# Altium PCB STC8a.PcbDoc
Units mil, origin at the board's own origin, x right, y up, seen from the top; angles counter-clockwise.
Board outline 3926.03 x 2520.03 mil, 2 copper layers (Top Layer, Bottom Layer); 127 components, 97 nets, 398 pads, 107 vias.
Unrouted connection lines stored in the file: 1.
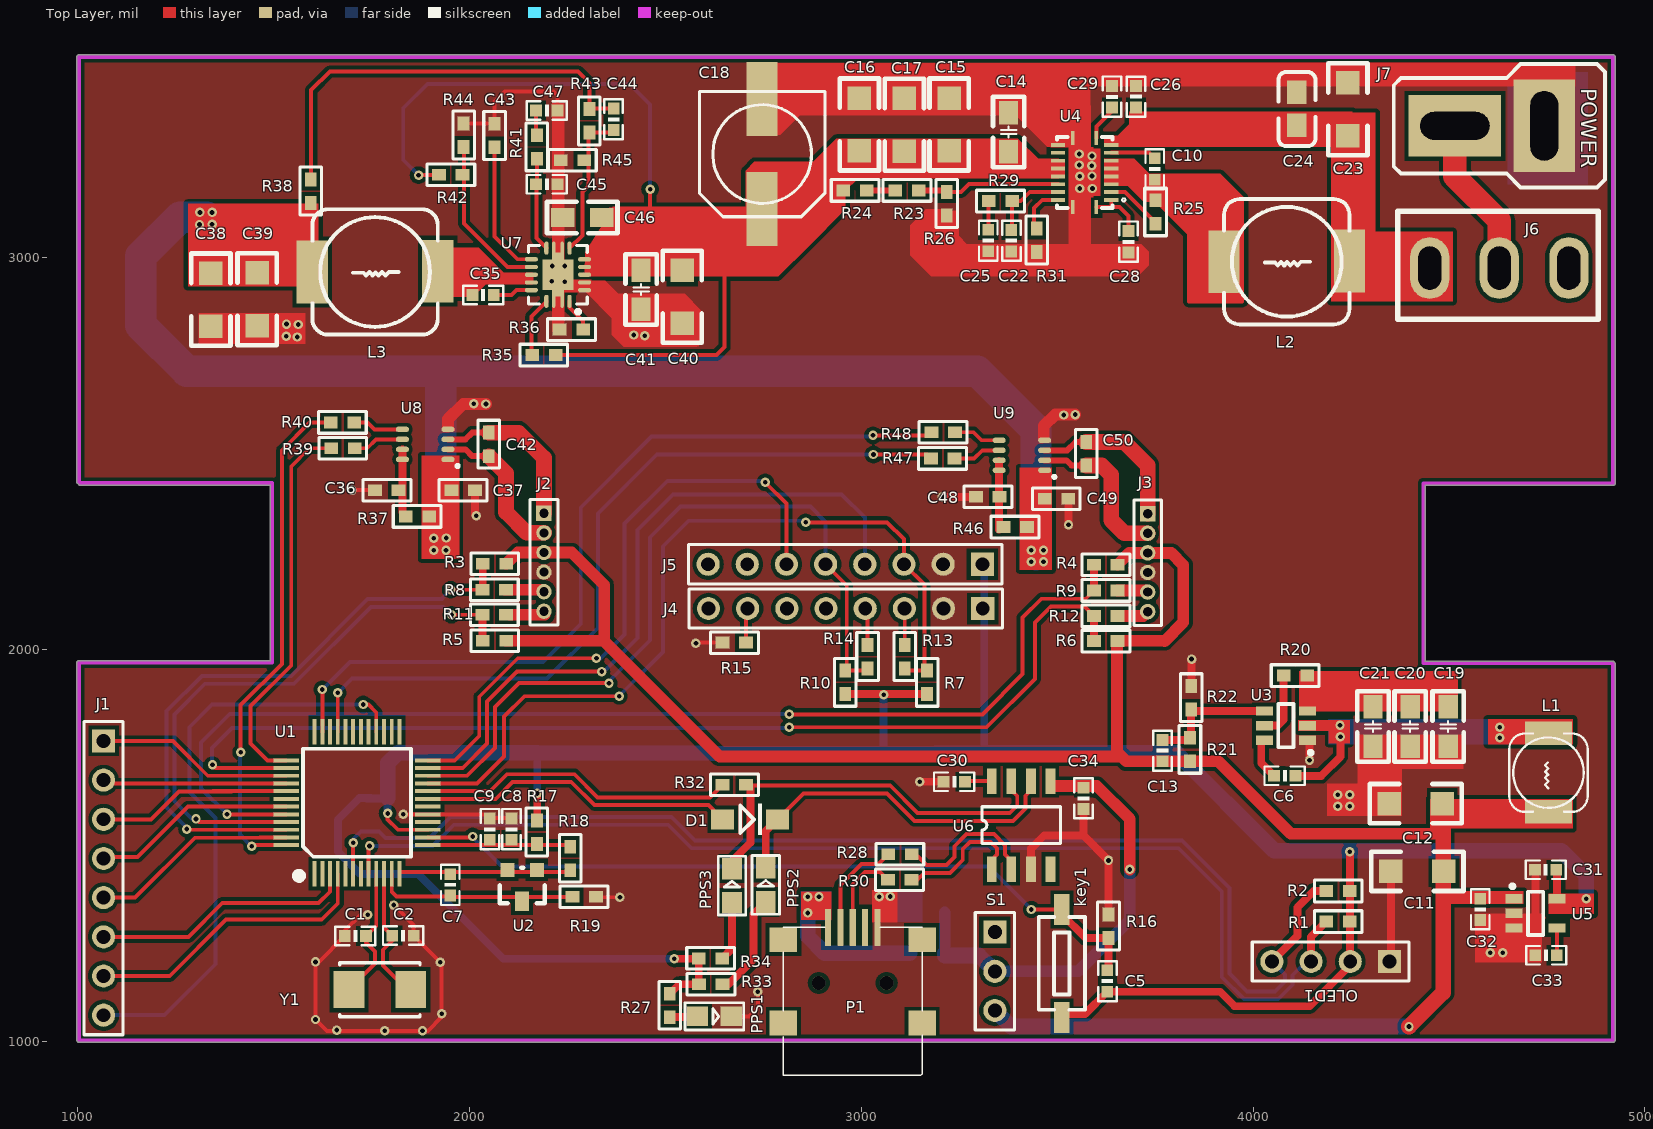
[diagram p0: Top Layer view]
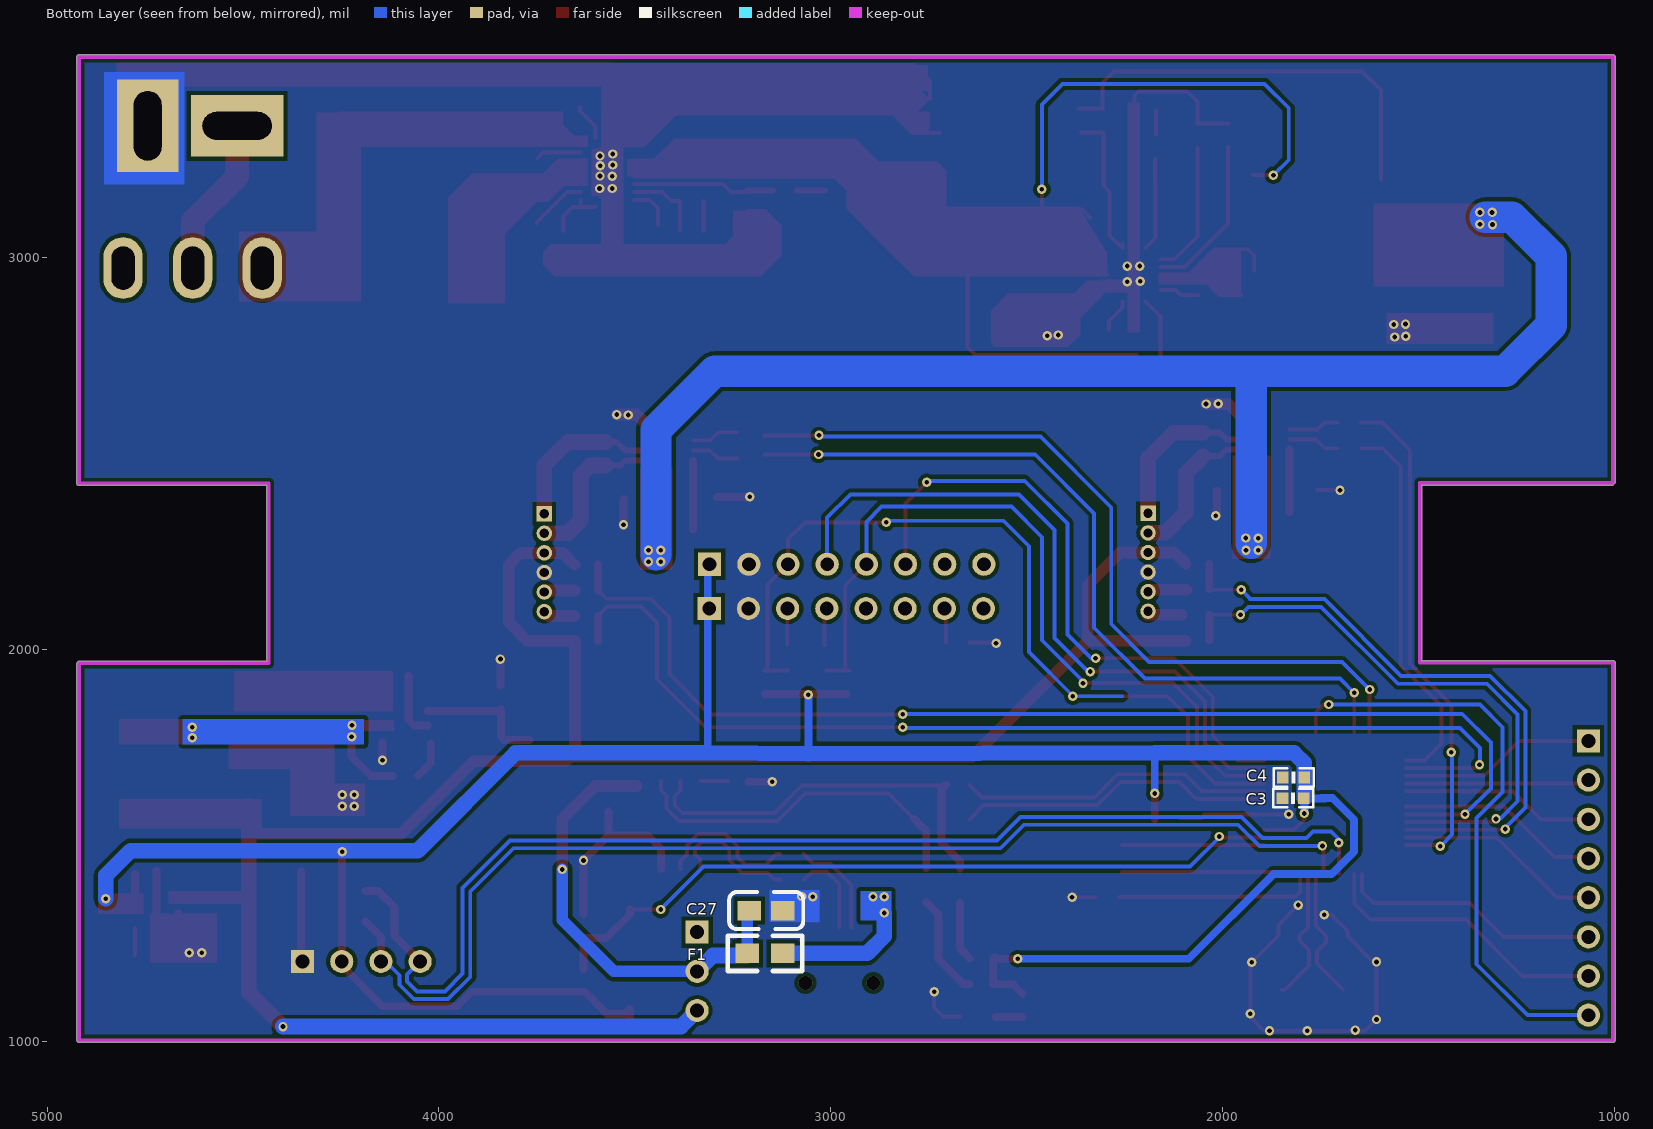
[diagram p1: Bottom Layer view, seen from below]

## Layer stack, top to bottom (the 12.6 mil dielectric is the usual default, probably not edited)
Top Solder: solder mask 0.4, Solder Resist, Dk 3.5
Top Layer: signal copper 1.4
Dielectric 1: dielectric 12.6, FR-4, Dk 4.8
Bottom Layer: signal copper 1.4
Bottom Solder: solder mask 0.4, Solder Resist, Dk 3.5

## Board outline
1003,997.99 cw(c1003,1003) 997.99,1003 997.99,1965 cw(c1003,1965) 998.09,1966 cw(c1003,1967) 1003,1972.02 1490.98,1972.02 1490.98,2419.99 1006,2419.99 cw(c1006,2425) 1002.44,2421.47 1002.45,2421.45 999.45,2424.45 999.47,2424.44 cw(c1003,2428) 997.99,2428 997.99,3513 cw(c1003,3513) 1003,3518.01 4919,3518.01 cw(c4919,3513) 4924.02,3513 4924.02,2424 cw(c4919,2424) 4919,2418.99 4440.02,2418.99 4440.02,1971.02 4917,1971.02 cw(c4917,1966) 4921.4,1968.4 cw(c4919,1964) 4924.02,1964 4924.02,1003 cw(c4919,1003) 4919,997.99

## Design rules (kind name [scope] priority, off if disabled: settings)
Clearance [All] p1: gap=10
PlaneConnect [All] p1: planeconnectstyle=Direct reliefexpansion=20 reliefentries=4 reliefconductorwidth=10 reliefairgap=10
PolygonConnect [All] p1: connectstyle=Direct reliefconductorwidth=10 reliefentries=4 polygonreliefangle="90 Angle" airgapwidth=10
RoutingVias [All] p1: holewidth=28 width=50 viastyle="Through Hole" minholewidth=28 minwidth=50 maxholewidth=28 maxwidth=50
SolderMaskExpansion [All] p1: expansion=4
Width [All] p1: maxlimit=80 minlimit=10 preferedwidth=80 toplayer_maxwidth=60 toplayer_prefwidth=10 minimp=50.000000 maximp=50.000000 favimp=50.000000
29 further rules are at their usual default settings.

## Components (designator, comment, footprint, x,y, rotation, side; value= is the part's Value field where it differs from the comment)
C1 "22PF" 0603-C 1736,1269 r180 top
C2 "22PF" 0603-C 1803,1270 r0 top
C3 "" 0603-C 1847,1621 r180 bottom
C4 "" 0603-C 1846,1674 r180 bottom
C5 "104" 0603-C 3628.06,1181.5 r270 top
C6 "" 0603-c 4108,1678 r180 top
C7 "100nf" 0603-C 1951,1427 r270 top
C8 "10UF" 0603-C 2106.94,1514.5 r90 top
C9 "100NF" 0603-C 2051.94,1514.5 r90 top
C10 "" 0603-c 3749,3254 r270 top
C11 "" 1206 4352,1434 r0 top
C12 "" 1206 4348,1607 r0 top
C13 "" 0603-c 3769.06,1769.5 r270 top
C14 "" 0805C 3376,3371 r270 top
C15 "" 1206 3224,3408 r270 top
C16 "" 1206 2995,3408 r270 top
C17 "" 1206 3110,3407 r270 top
C18 "" CC88 2747,3265 r90 top
C19 "" 0805c 4498,1854 r270 top
C20 "" 0805c 4401,1854 r270 top
C21 "" 0805c 4306,1854 r270 top
C22 "" 0603-C 3383,3071 r270 top
C23 "" 1206 4242,3312 r90 top
C24 "" 0805-c 4112,3423 r270 top
C25 "" 0603-C 3324.06,3071.5 r270 top
C26 "" 0603-c 3701.06,3438.5 r270 top
C27 "10uF" 0805-C 3208,1334 r180 bottom
C28 "" 0603-c 3682,3014 r90 top
C29 "" 0603-C 3640,3384 r90 top
C30 "0.1uf" 0603-C 3264.5,1662.94 r180 top
C31 "" 0603-C 4719.5,1438.06 r0 top
C32 "" 0603-C 4580,1310 r90 top
C33 "" 0603-C 4720.5,1220.06 r0 top
C34 "0.1uf" 0603-C 3567,1593 r90 top
C35 "" 0603-c 2007.5,2905.06 r0 top
C36 "0.1UF" 0603-r 1819,2407 r180 top
C37 "0.1UF" 0603-r 1954,2407 r0 top
C38 "" 1206 1340,2826 r90 top
C39 "" 1206 1458,2827 r90 top
C40 "" 1206 2543,2968 r270 top
C41 "" 0805c 2438,2869 r90 top
C42 "104" 0603-r 2049,2554 r270 top
C43 "" 0603-r 2064,3342 r270 top
C44 "" 0603-c 2367.94,3326.5 r90 top
C45 "" 0603-c 2224.5,3187.94 r180 top
C46 "" 0805r 2238,3103 r0 top
C47 "" 0603-c 2224.5,3375.94 r180 top
C48 "0.1UF" 0603-r 3353,2390 r180 top
C49 "0.1UF" 0603-r 3468,2385 r0 top
C50 "104" 0603-r 3574,2530 r270 top
D1 "二极管" DIODE_SOP 2646,1567 r0 top
F1 "500mA保险丝" "0805 - duplicate" 3123,1224.94 r0 bottom
J1 "CON8" HDR1X8 1066,1767 r270 top
J2 "CON6" MHDR1X6 2190,2348 r270 top
J3 "CON6" MHDR1X6 3731,2347 r270 top
J4 "CON8" HDR1X8 3310,2105 r180 top
J5 "CON8" HDR1X8 3309,2218 r180 top
J6 "主开关" 拨动开关 4626,2979 r90 top
J7 "T插" T型头 4642,3329 r180 top
key1 "KEY" KEY 3512,1199 r0 top
L1 "Inductor" L5*5 4754,1586 r90 top
L2 "PIMB   0630" L8*8 4246,2990 r180 top
L3 "Inductor" L8*8 1919,2964 r180 top
OLED1 "CON4" HDR1X4 4348,1204 r180 top
P1 "USB_Micro" "USB_MINI - duplicate" 2978.16,913.14 r90 top
PPS1 "LED" 0805-LED 2629,1064 r0 top
PPS2 "LED" 0805-LED 2756,1403.63 r90 top
PPS3 "LED" 0805-LED 2670,1401.64 r90 top
R1 "" 0603-R 4247,1306 r180 top
R2 "" 0603-R 4247,1384 r180 top
R3 "10K" 0603-R 2094,2219 r180 top
R4 "10K" 0603-R 3654,2217 r180 top
R5 "10K" 0603-R 2094,2023 r180 top
R6 "10K" 0603-R 3654,2022 r180 top
R7 "" 0603-R 3168,1887 r90 top
R8 "510R" 0603-R 2093,2153 r180 top
R9 "510R" 0603-R 3654,2151 r180 top
R10 "" 0603-R 2959,1887 r90 top
R11 "510R" 0603-R 2093,2089 r180 top
R12 "510R" 0603-R 3654,2086 r180 top
R13 "200R" 0603-R 3111,2012 r270 top
R14 "200R" 0603-R 3016,2012 r270 top
R15 "4.7k" 0603-R 2706,2018 r180 top
R16 "10k" 0603-R 3631,1324 r270 top
R17 "Res1" 0603-R 2172,1564 r270 top
R18 "Res1" 0603-R 2257,1497 r270 top
R19 "Res1" 0603-R 2263,1369 r0 top
R20 "" 0603-r 4078,1934 r0 top
R21 "" 0603-r 3839,1775 r270 top
R22 "" 0603-r 3842,1907 r270 top
R23 "Res1" 0603-R 3087,3172 r0 top
R24 "Res1" 0603-R 3014,3172 r180 top
R25 "" 0603-r 3751,3147 r270 top
R26 "Res1" 0603-R 3218,3168 r270 top
R27 "1K" 0603-R 2511,1122 r270 top
R28 "22R" 0603-R 3069,1478 r0 top
R29 "" 0603-R 3385,3145 r180 top
R30 "22R" 0603-R 3068,1413 r0 top
R31 "Res1" 0603-R 3448,3075 r270 top
R32 "300R" 0603-R 2706,1655 r180 top
R33 "1K" 0603-R 2646,1146 r180 top
R34 "1K" 0603-R 2645,1212 r180 top
R35 "" 0603-r 2160,2752 r0 top
R36 "" 0603-r 2290,2817 r180 top
R37 "1K" 0603-r 1837,2340 r0 top
R38 "" 0603-r 1595,3200 r270 top
R39 "200Ω" 0603-r 1647,2514 r0 top
R40 "200Ω" 0603-r 1646,2580 r0 top
R41 "Res1" 0603-r 2172,3313 r270 top
R42 "" 0603-r 1982,3212 r180 top
R43 "" 0603-r 2306,3320 r90 top
R44 "" 0603-r 1985,3343 r270 top
R45 "" 0603-r 2233,3249 r0 top
R46 "1K" 0603-r 3363,2313 r0 top
R47 "200Ω" 0603-r 3178,2488 r0 top
R48 "200Ω" 0603-r 3179,2555 r0 top
S1 "switch" HDR1X3 3341,1279 r270 top
U1 "STC8A8K64S4A12-48" LQFP48S 1604.92,1427.69 r90 top
U2 "TL431" SOT-23 2172,1438 r180 top
U3 "TPS562201" LC-SOT-23-6 4084,1806 r0 top
U4 "TPS61088" VQFN-20_L4.6-W3.6-P0.50-BL 3570,3218 r90 top
U5 "TPS79133" LC-SOT-23-5 4721,1327 r180 top
U6 "CH340N" SOP-8 3333,1440 r90 top
U7 "TPS54821" LC-VQFN-14_3.6x3.6x05P 2225.83,2957 r90 top
U8 "drv8837" LC-WSON-8_2x2mm 1887,2524 r90 top
U9 "drv8837" LC-WSON-8_2x2mm 3410,2496 r90 top
Y1 "XTAL_5032" XTAL_5032 1771.26,1132 r180 top

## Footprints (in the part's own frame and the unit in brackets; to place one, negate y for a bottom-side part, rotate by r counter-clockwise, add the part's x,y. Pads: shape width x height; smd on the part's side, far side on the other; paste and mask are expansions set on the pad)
0603-C [mil]
  rect 30x30 smd: 1(0,0) 2(54.5,-0.06)
  silkscreen extent -24,-24 79,24
0603-c [mil]
  rect 30x30 smd: 1(0,0) 2(54.5,-0.06)
  silkscreen extent -24,-24 79,24
0603-r [mil]
  rect 35x30 smd: 1(0,0) 2(60,0)
  silkscreen extent -31,-28 91,28, body extent -22,-19 82,19, height 39
0603-R [mil]
  rect 35x30 smd: 1(0,0) 2(60,0)
  silkscreen extent -31,-28 91,28, body extent -22,-19 82,19, height 39
"0805 - duplicate" [mil]
  rect 60x50 smd: 1(0,-0.06) 2(90,-0.06)
  silkscreen extent -50,-45 140,45
0805-c [mil]
  rect 60x50 smd: 1(0,0) 2(85,0)
  silkscreen extent -51,-47 138,47, body extent 3,-25 82,25, height 30
0805-C [mil]
  rect 60x50 smd: 1(0,0) 2(85,0)
  silkscreen extent -51,-47 138,47, body extent 3,-25 82,25, height 30
0805-LED [mm]
  rect 1.4x1.27 smd: 1(-1.21,0) 2(1,0)
  silkscreen extent -2.01,-0.89 1.8,0.89
0805C [mil]
  rect 60x49.21 smd: 1(0,0) 2(100,0)
  silkscreen extent -40,-40 140,40
0805c [mil]
  rect 60x49.21 smd: 1(0,0) 2(100,0)
  silkscreen extent -40,-40 140,40
0805r [mil]
  rect 60x49.21 smd: 1(0,0) 2(100,0)
  silkscreen extent -40,-40 140,40
1206 [mil]
  rect 60x60 smd: 1(0,0) 2(135,0)
  silkscreen extent -50,-50 185,50
CC88 [mm] "SMD;W:8mm;L:8mm;"
  rect 4.8x2 smd: 1(-3.556,0) 2(3.556,0)
  silkscreen extent -4.06,-4.06 4.06,4.06
DIODE_SOP [mm]
  rect 1.5x1.3 smd: 1(0,0) 2(3.556,0)
  silkscreen extent 1.14,-1.02 2.56,1.02
HDR1X3 [mm] "Connector; Header; 3 Position"
  rect 1.5x1.5 hole 0.9: 1(0,0)
  round 1.5 hole 0.9: 2(2.54,0) 3(5.08,0)
  silkscreen extent -1.27,-1.27 6.35,1.27
HDR1X4 [mm] "Connector; Header; 4 Position"
  rect 1.5x1.5 hole 0.9: 1(0,0)
  round 1.5 hole 0.9: 2(2.54,0) 3(5.08,0) 4(7.62,0)
  silkscreen extent -1.27,-1.27 8.89,1.27
HDR1X8 [mm] "Connector; Header; 8 Position"
  rect 1.5x1.5 hole 0.9: 1(0,0)
  round 1.5 hole 0.9: 2(2.54,0) 3(5.08,0) 4(7.62,0) 5(10.16,0) 6(12.7,0) 7(15.24,0) 8(17.78,0)
  silkscreen extent -1.27,-1.27 19.05,1.27
KEY [mm]
  rect 1x2 smd: 1(0,3.5) 2(0,-3.5)
  silkscreen extent -1.5,-3 1.5,3
L5*5 [mil]
  rect 60x120 smd: 1(0,0) 2(200,0)
  silkscreen extent 0,-100 200,100
L8*8 [mil]
  rect 80x160 smd: 1(0,-2) 2(320,0)
  silkscreen extent 0,-160 320,160
LC-SOT-23-5 [mm]
  rect 1.1x0.6 smd: 1(1.4,-0.95) 2(1.4,0) 3(1.4,0.95) 4(-1.4,0.95) 5(-1.4,-0.95)
  silkscreen extent -0.5,-1.87 1.62,1.4
LC-SOT-23-6 [mm]
  rect 1.1x0.6 smd: 1(1.4,-0.95) 2(1.4,0) 3(1.4,0.95) 4(-1.4,0.95) 5(-1.4,0) 6(-1.4,-0.95)
  silkscreen extent -0.5,-1.87 1.73,1.4
LC-VQFN-14_3.6x3.6x05P [mm]
  rect 2.85x0.35 smd mask+0.051: 0(0,0)
  rect 2x2 smd mask+0.051: 0(0,0)
  oval 0.85x0.28 smd mask+0.051: 1(-1.725,-0.75) 7(1.725,-0.753) 8(1.725,0.75) 14(-1.725,0.75)
  oval 0.28x0.85 smd mask+0.051: 2(-1,-1.725) 3(-0.5,-1.725) 4(0,-1.725) 5(0.5,-1.725) 6(1,-1.725) 9(1,1.725) 10(0.5,1.725) 11(0,1.725) 12(-0.5,1.725) 13(-1,1.725)
  oval 4.3x0.2 smd mask+0.051: ""(0,0.275) ""(0,-0.275)
  silkscreen extent -2.52,-1.9 1.9,1.9
LC-WSON-8_2x2mm [mm]
  oval 0.35x0.85 smd mask+0.051: 1(-0.975,-1.475) 2(-0.325,-1.475) 3(0.325,-1.475) 4(0.975,-1.475) 5(0.975,1.475) 6(0.325,1.475) 7(-0.325,1.475) 8(-0.975,1.475)
  silkscreen extent -1.5,-2.2 -1.3,-2
LQFP48S [mil] "DPIN-0.5"
  rect 65x10 smd: 1(0.42,0.29) 2(0.42,-19.39) 3(0.42,-39.08) 4(0.42,-58.76) 5(0.42,-78.45) 6(0.42,-98.13) 7(0.42,-117.82) 8(0.42,-137.5) 9(0.42,-157.19) 10(0.42,-176.87) 11(0.42,-196.56) 12(0.42,-216.24) 25(362.63,-216.24) 26(362.63,-196.56) 27(362.63,-176.87) 28(362.63,-157.19) 29(362.63,-137.5) 30(362.63,-117.82) 31(362.63,-98.13) 32(362.63,-78.45) 33(362.63,-58.76) 34(362.63,-39.08) 35(362.63,-19.39) 36(362.63,0.29)
  rect 10x65 smd: 13(73.26,-289.08) 14(92.94,-289.08) 15(112.63,-289.08) 16(132.31,-289.08) 17(152,-289.08) 18(171.68,-289.08) 19(191.37,-289.08) 20(211.05,-289.08) 21(230.74,-289.08) 22(250.42,-289.08) 23(270.11,-289.08) 24(289.79,-289.08) 37(289.79,73.13) 38(270.11,73.13) 39(250.42,73.13) 40(230.74,73.13) 41(211.05,73.13) 42(191.37,73.13) 43(171.68,73.13) 44(152,73.13) 45(132.31,73.13) 46(112.63,73.13) 47(92.94,73.13) 48(73.26,73.13)
  silkscreen extent -10,-246 319,46
MHDR1X6 [mm] "Connector; Header; 6 Position"
  rect 1x1 hole 0.6: 1(0,0)
  round 1 hole 0.6: 2(1.27,0) 3(2.54,0) 4(3.81,0) 5(5.08,0) 6(6.35,0)
  silkscreen extent -0.9,-0.9 7.25,0.9
SOP-8 [mil]
  rect 65x25 smd: 1(0,0) 2(0,-50) 3(0,-100) 4(0,-150) 5(224.41,-150) 6(224.41,-100) 7(224.41,-50) 8(224.41,0)
  silkscreen extent 65,-175 159,25
SOT-23 [mil]
  rect 36x36 smd: 1(0,0) 2(75,0)
  rect 36x50 smd: 3(38,80)
  silkscreen extent -20,-5 95,85
T型头 [mm]
  rect 4x6 hole 1.8 slot 4.5 at 90 deg: 1(-2.574,-0.203)
  rect 6x4 hole 1.8 slot 4.5 at 0 deg: 2(3.226,-0.203)
  silkscreen extent -6.51,-4.2 7.19,3.8
"USB_MINI - duplicate" [mm]
  rect 1.6x1.8 smd: 0(3.4,-4.5) 0(3.4,4.5) 0(8.8,-4.5) 0(8.8,4.5)
  rect 2.4x0.4 smd: 1(9.6,1.6) 2(9.6,0.8) 3(9.6,0) 4(9.6,-0.8) 5(9.6,-1.6)
  silkscreen extent 0,-4.5 9.6,4.5
VQFN-20_L4.6-W3.6-P0.50-BL [mil]
  rect 36x9.6 smd: 1(-88,-30) 10(88,-30) 11(88,30) 20(-88,30)
  rect 9.6x36 smd: 2(-70,-68) 3(-50,-68) 4(-30,-68) 5(-10,-68) 6(10,-68) 7(30,-68) 8(50.4,-68) 9(70,-68) 12(70,68) 13(50,68) 14(30,68) 15(10,68) 16(-10,68) 17(-30,68) 18(-50,68) 19(-70,68)
  round 0 smd: 21(-0.08,0.02)
  Top Layer region: -63.9,5.63 -97.91,5.75 -97.91,14.8 -63.9,14.96 -63.78,22.24 -60,22.28 -59.96,40 60,40 59.88,22.48 63.74,22.48 63.86,15 97.76,15 97.76,5.79 63.74,5.79 63.86,-5.39 97.76,-5.39 97.76,-14.61 63.74,-14.61 63.86,-22.09 60,-22.09 60,-39.92 -60,-40 -60,-22.32 -63.86,-22.32 -63.82,-14.72 -97.76,-14.72 -97.72,-5.63 -63.78,-5.67 -63.82,5.71
  silkscreen extent -91,-104 91,71
XTAL_5032 [mm]
  rect 2x2.4 smd: 1(-2,0) 2(2,0)
  silkscreen extent -2.6,-1.75 2.6,1.75, body extent -2.5,-1.6 2.5,1.6, height 1
拨动开关 [mm]
  oval 4x2.54 hole 1.5 slot 2.8 at 0 deg: 1(-0.127,-0.064) 2(-0.127,4.445) 3(-0.127,-4.572)
  silkscreen extent -3.44,-6.48 3.56,6.52

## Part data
C1 C2 C5 C36 C37 C42 C48 C49 C50: library part CAP_0805
C3 C4 C6 C10 C11 C12 C13 C14 C15 C16 C17 C19 C20 C21 C22 C24 C25 C26 C28 C29 C31 C32 C33 C35 C38 C39 C41 C43 C44 C45 C46 C47: library part Cap, "Capacitor"
C7 C8 C9 C27 C30 C34: library part CAP
C18 C23 C40: library part "Cap Pol1", "Polarized Capacitor (Radial)"
D1: library part D_1, "1N4148"
F1: library part "Fuse 2", "Fuse"
J6: library part CON3
J7: library part CON2
L2: library part Inductor, "Inductor"
P1: "USB"
R1 R2 R7 R10 R20 R21 R22 R25 R29 R35 R36 R38 R42 R43 R44 R45: library part Res1, "Resistor"
R3 R4 R5 R6 R8 R9 R11 R12 R13 R14 R15 R16 R27 R28 R30 R32 R33 R34 R37 R39 R40 R46 R47 R48: library part RES, "Resistor"
R17 R18 R19 R23 R24 R26 R31 R41: "Resistor"
S1: library part "SW DPDT", "Switch"
U4: library part TPS61008
U8 U9: library part DRV8837DSGR
Y1: "Crystal Oscillator"

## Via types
v1: diameter 24, hole 12, Top Layer to Bottom Layer, tented both sides, 105 vias
v2: diameter 35.43, hole 35.43, Top Layer to Bottom Layer, 2 vias

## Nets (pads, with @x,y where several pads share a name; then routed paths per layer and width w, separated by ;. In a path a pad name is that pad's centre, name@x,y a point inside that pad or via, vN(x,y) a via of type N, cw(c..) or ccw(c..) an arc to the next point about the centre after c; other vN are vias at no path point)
12V-VCC: C14.2 C15.2 C16.2 C17.2 C18.1 C40.1 C41.2 C46.2 R24.2 R35.2 R42.2 U4.14 U4.15 U4.16 U7.4 U7.5 U7.6 | length 4840.8
  Top Layer w10: v1@1871,3212 R42.2 ; R35.2 2630,2752 2651,2773 2651,2957 ; U7.4 2543,2957 2651,2957 ; C46.2 2358,3123 2461,3123 ; 2461,3104 2461,3123 ; v1(2461,3175) 2461,3123 ; 2651,2988 2651,2957 ; C18.1@2745,3123 C18.1@2709,3123 ; 2461,3123 C18.1@2709,3123 ; 2651,2957 2786,2957 2861,3032 ; C18.1@2709,3123 2709,3032 2861,3032 ; C18.1@2709,3123 2709,3221 2729,3241 2879,3241 2938,3300 3110,3300 3398,3300 3450,3248 U4.14 U4.16 2990,3208 2955,3173 2955,3126 2861,3032
  Bottom Layer w10: v1(1870,3211) 1831,3250 1831,3382 1893,3444 2408,3444 2461,3391 v1(2461,3175)
AD0: J4.7 R15.1 | length 83
  Top Layer w10: R15.1 J4.7@2706,2101
AGND: C7.2 R19.1 U1.11 U2.3 | length 514.4
  Top Layer w10: 1801.48,1381.52 U1.11 ; 1801.8,1381.52 1801.8,1381.2 1813.5,1369.5 C7.2@1950.94,1369.5 ; C7.2 1954.44,1369 R19.1
AVCC: C8.1 C9.1 R17.2 R18.1 U1.13 | length 363
  Top Layer w10: U1.13 R18.1@2257,1500.94
BOOST_IN: C23.1 C24.2 C26.2 J6.2 L2.1 U4.9 | length 233.7
  Top Layer w10: 3656,3307 3689,3340
  Top Layer w60: L2.1@4264,2974 J6.2
CS: J5.6 U1.24 | length 1613
  Top Layer w10: U1.24 1962.48,1717.48 2025,1780 2025,1879.85 2123.15,1978 v1(2324,1978) ; v1(2755,2427) 2809,2373 J5.6
  Bottom Layer w10: v1(2324,1978) 2333,1978 2334,1977 2396,2039 2396,2322 2505,2431 v1@2755,2431
DRV-6V: C37.1 C38.2 C39.2 C49.1 L3.2 R37.2 R38.2 R46.2 U8.1 U9.1 | length 3536
  Bottom Layer w80: 1329,3104 1312,3104 1261,3104 1161,3004 1161,2828 1278,2711 3296,2711 3446,2561 3446,2242 ; 1927,2271 1927,2707
  other v1: 3434,2224 3465,2224 1909,2254 1940,2254 3434,2254 3465,2254 1909,2284 1941,2285 1311,3085 1343,3086 1312,3116 1343,3116
EN: R42.1 R44.2 U7.10 | length 413.6
  Top Layer w10: R44.2 1986,3282 1986,3087.69 2097,2976.69 U7.10
EN1: C19.1 C20.1 C21.1 R20.2 U3.3
FSY: J5.8
GND: C1.2 C2.2 C3.1 C4.1 C8.2 C9.2 C11.1 C12.1 C14.1 C15.1 C16.1 C17.1 C18.2 C19.2 C20.2 C21.2 C22.2 C23.2 C24.1 C25.2 C26.1 C27.2 C28.1 C29.2 C30.2 C31.1 C32.1 C33.1 C34.1 C36.2 C37.2 C38.1 C39.1 C40.2 C41.1 C43.1 C45.1 C46.1 C47.1 C48.2 C49.2 J2.4 J3.4 J4.2 J5.2 J7.1 OLED1.1 P1.5 PPS1.2 R15.2 R16.1 R19.2 R22.1 R26.2 R31.2 R36.2 R44.1 R45.1 U1.17 U3.1 U4.11 U4.12 U4.20 U4.21 U5.2 U5.3 U6.3 U7.2 U7.3 U8.4 U9.4 | length 7603.3
  Top Layer w10: v1(1700,2407) C36.2 ; v1(1740,1323) 1722,1323 1681.5,1282.5 C1.2 1615.44,1203 v1(1607,1203) v1(1607,1056) 1636,1027 v1(1784,1027) v1(1880,1027) 1894,1027 1929,1062 v1(1929,1071) 1929,1198.44 v1(1925,1202.44) C2.2 1857.5,1297.5 v1(1807,1348) ; v1(1830.68,1579.68) U1.17 C9.2@2047,1579.68 ; U8.4 U8.4@1957.39,2562.39 ; R44.1 C43.1@2063,3343 ; C9.2@2053,1570 C8.2@2108,1570 ; C43.1 2064,3399 2090,3425 2214,3425 2224.5,3414.5 C47.1 ; 2238,3065.84 C46.1 ; U7.2 2298.37,2917.63 2368,2848 2368,2806 2396,2778 2578,2778 2586,2786 2586,2865 2547,2904 2378,2904 2345,2937 2316.98,2937 ; U7.3 2323.68,2937.32 ; R19.2@2324,1368 v1(2384,1368) ; v1@2580,2018 R15.2 ; PPS1.2 2713,1064 2736,1087 v1(2736,1127) ; C18.2@2721,3319 2792,3319 2842,3369 3395,3369 3476,3288 U4.12 ; C18.2 2747,3453 2787,3493 3512,3493 ; R26.2@3213,3120 3167,3120 3129,3082 3129,3009 3181,2957 3704,2957 3730,2983 3730,3014 3713,3031 3382.94,3031 3268,3031 3245,3054 3245,3116 3226,3116 R26.2 ; U4.20@3537.76,3143 3540,3140.76 U4.20 ; U4.11@3540,3295.43 U4.11 ; C34.1@3567,1587 C34.1
  Top Layer w20: v1@2014,2345 C37.2 ; v1(3149,1663) C30.2 ; v1(3207,2390) C48.2@3290,2390 ; U6.3 3433,1492 3467,1526 3567,1526 ; C49.2 3529,2384 v1(3529,2319) ; C34.1@3567,1587 3567,1526 ; R16.1 v1(3631,1462) 3567,1526 ; R22.1@3843,1908 v1(3843,1976) ; v1(4144,1718) U3.1@4144,1763.72 ; OLED1.1@4352,1204 C11.1 ; C32.1 4664.88,1310 ; U5.3 U5.2 ; C33.1 C31.1@4720.5,1437.06
  Top Layer w30: 1945.07,2569.61 1945.07,2588.07 1984,2627 v1(2042,2627) ; 3466,2543 3466,2571 3495,2600 v1(3546,2600)
  other v1: 1661,1029 4605,1226 4637,1226 3046,1369 3074,1370 4216,1600 4247,1600 4216,1630 4247,1630 2578,2016 2017,2342 3517,2599 2011,2628 1560,2798 1532,2800 2447,2801 2419,2803 1563,2830 1533,2831 2243,2939 2210,2940 2211,2979 2243,2979 3558,3177 3590,3177 3558,3208 3589,3209 3588,3235 3556,3237 3589,3260 3556,3265
INT: J4.8
INT1: J5.7
NetC6_1: C6.1 L1.2 U3.2 | length 176.3
  Top Layer w20: C6.1@4118,1677.94 4173.94,1677.94 4223,1727 v1(4223,1778)
  other v1: 4630,1775 4222,1807
NetC6_2: C6.2 U3.6 | length 96.1
  Top Layer w20: U3.6@4021,1760.72 4021,1710.56 C6.2
NetC10_1: C10.1 U4.8 | length 117
  Top Layer w10: U4.8 3734.6,3268.4 C10.1
NetC10_2: C10.2 L2.2 R25.1 U4.4 U4.5 U4.6 U4.7 | length 1196
  Top Layer w10: U4.4 3682,3188 3723,3147 R25.1 3837,3061 3837,2889 3972,2889 3972,3153 3915,3210 3733,3210 3695,3248 U4.7
NetC13_1: C13.1 R21.1 R22.2 U3.4 | length 320.3
  Top Layer w20: C13.1 R21.1@3833.5,1769.5 ; R21.1@3842,1778 R22.2@3842,1843.4 ; R22.2 R22.2@3842,1843.4 ; U3.4 R22.2@3842,1843.4
NetC22_1: C22.1 R29.1 U4.18 | length 200.5
  Top Layer w10: C22.1@3385,3071 R29.1 3407,3145 3430,3168 U4.18
NetC25_1: C25.1 R29.2 | length 76.5
  Top Layer w10: C25.1@3325,3068.5 R29.2
NetC28_2: C28.2 U4.1 U4.2 | length 147
  Top Layer w10: U4.1 3659,3130 3682,3107 C28.2@3682,3068.5 ; 3638,3131 U4.2
NetC29_1: C29.1 U4.10 | length 94.6
  Top Layer w10: U4.10 3600,3335 3640,3375 C29.1
NetC30_1: C30.1 U6.8 | length 71.4
  Top Layer w10: C30.1@3261.59,1664.41 U6.8
NetC33_2: C33.2 U5.4 | length 68.5
  Top Layer w10: C33.2@4776.12,1221.12 U5.4
NetC35_1: C35.1 L3.1 U7.11 U7.12 | length 550.4
  Top Layer w10: L3.1 1919,3006 1935,3022 2022,3022 2087,2957 U7.11 U7.12 2039.75,2937.32 C35.1 L3.1@1953,2905.06
NetC35_2: C35.2 U7.13 | length 101.1
  Top Layer w10: C35.2 2107,2905 2119.63,2917.63 U7.13
NetC36_1: C36.1 R37.1 U8.7 U8.8 | length 160.1
  Top Layer w20: R37.1@1828.93,2351.07 U8.8 U8.7
NetC43_2: C43.2 U7.9 | length 345.2
  Top Layer w10: C43.2 2064,3055 2122.63,2996.37 U7.9
NetC44_2: C44.2 R38.1 R43.2 | length 1097.9
  Top Layer w10: R38.1@1596,3200 1596,3428 1644,3476 2277,3476 2306,3447 R43.2 ; R43.2@2307,3381 C44.2
NetC45_2: C45.2 R41.2 U7.8 | length 239
  Top Layer w10: R41.2 2172,3190 2171,3189 2171,3050.21 U7.8
NetC47_2: C47.2 R41.1 | length 61
  Top Layer w10: R41.1@2170,3315 C47.2
NetC48_1: C48.1 R46.1 U9.7 U9.8 | length 175.7
  Top Layer w20: R46.1@3351.93,2305.93 3351.93,2390 U9.8 U9.7@3351.93,2481.61
NetF1_1: F1.1 P1.1 | length 378.2
  Bottom Layer w30: v1(2863,1328) v1(2863,1369)
  Bottom Layer w40: v1(2863,1328) 2863,1269 2907,1225 F1.1
  other v1: 2892,1369
NetJ2_5: J2.5 R8.1 | length 92
  Top Layer w30: R8.1@2091,2153 J2.5@2183,2153
NetJ2_6: J2.6 R11.1 | length 88
  Top Layer w30: R11.1@2104,2089 J2.6@2192,2089
NetJ3_5: J3.5 R9.1 | length 73
  Top Layer w30: R9.1 J3.5@3727,2151
NetJ3_6: J3.6 R12.1 | length 81.6
  Top Layer w30: R12.1 3720,2086 J3.6
NetJ4_3: J4.3 R13.1 | length 92
  Top Layer w10: R13.1 J4.3@3111,2104
NetJ4_4: J4.4 R14.1 | length 87
  Top Layer w10: R14.1 J4.4@3016,2099
NetP1_2: P1.2 R28.1 | length 262.9
  Top Layer w10: P1.2 2946.67,1398.95 3000.72,1453 3044,1453 R28.1
NetP1_3: P1.3 R30.1 | length 222
  Top Layer w10: P1.3 2978.16,1402.16 3009,1433 3048,1433 R30.1
NetPPS1_1: PPS1.1 R27.2 | length 68.4
  Top Layer w20: R27.2 PPS1.1@2579.36,1062
NetPPS2_1: PPS2.1 R33.1 | length 264.3
  Top Layer w20: R33.1 2661,1146 2725,1210 2725,1324.99 PPS2.1
NetPPS3_1: PPS3.1 R34.1 | length 152.4
  Top Layer w20: R34.1 2670,1237 PPS3.1
NetR20_1: R20.1 U3.5 | length 168.3
  Top Layer w20: U3.5 4063,1806 4078,1821 R20.1
NetR23_1: R23.1 R24.1 | length 73
  Top Layer w15: R24.1 R23.1
NetR23_2: R23.2 R26.1 U4.17 | length 359.3
  Top Layer w10: R26.1 3255,3168 3275,3188 U4.17
  Top Layer w15: R23.2 R26.1@3214,3172
NetR25_2: R25.2 U4.3 | length 148.3
  Top Layer w10: U4.3 3673,3168 3751,3090 R25.2
NetR31_1: R31.1 U4.19 | length 112.7
  Top Layer w10: R31.1@3441,3084 3441,3127 3462,3148 U4.19
NetR35_1: R35.1 U7.14 | length 153
  Top Layer w10: R35.1@2158,2752 2158,2850.79 U7.14
NetR36_1: R36.1 U7.1 | length 86.4
  Top Layer w10: U7.1 2255.35,2873.65 2290,2839 R36.1
NetR39_2: R39.2 U8.6 | length 131.4
  Top Layer w10: R39.2 1739,2514 1761.8,2536.8 U8.6
NetR40_2: R40.2 U8.5 | length 130.2
  Top Layer w10: R40.2 1740,2580 1757.61,2562.39 U8.5
NetR47_2: R47.2 U9.6 | length 122.5
  Top Layer w10: R47.2 3288,2488 3308.8,2508.8 U9.6
NetR48_2: R48.2 U9.5 | length 121.5
  Top Layer w10: R48.2 3286,2555 3306.61,2534.39 U9.5
OUT1+: C42.2 J2.2 U8.2 | length 391.2
  Top Layer w15: U8.2 1989.8,2511.2 2007,2494 C42.2
  Top Layer w40: C42.2 2093,2450 2093,2351 2146,2298 J2.2
OUT1-: C42.1 J2.1 U8.3 | length 420
  Top Layer w15: U8.3 1989.8,2536.8 2007,2554 C42.1
  Top Layer w40: C42.1 2125,2554 2190,2489 J2.1
OUT2+: C50.2 J3.2 U9.2 | length 408
  Top Layer w15: U9.2 3523.8,2483.2 3537,2470 C50.2
  Top Layer w40: C50.2 3614,2470 3638,2446 3638,2330 3671,2297 J3.2
OUT2-: C50.1 J3.1 U9.3 | length 419.6
  Top Layer w15: U9.3 3525.8,2508.8 3547,2530 C50.1
  Top Layer w40: C50.1 3671,2530 3731,2470 J3.1
OUT-5V: C11.2 C12.2 C13.2 C32.2 J2.3 J3.3 L1.1 R3.1 R4.1 R5.1 R6.1 R21.2 S1.3 U5.1 | length 5537
  Top Layer w30: R5.1 2343,2023 ; R3.1 2123,2248 J2.3 2261,2248 2344,2165 2344,2022 2639,1727 3654,1727 3653,1738 ; R4.1 3684,2247 J3.3 3791,2247 3822,2216 3822,2070 3774,2022 3654.01,2022.99 3653,2023 3653,1738 ; 4485,1530 4096,1530 3911,1715 R21.2 C13.2 3676,1715 3653,1738
  Top Layer w40: v1(4398,1038) 4485,1125 4485,1530 C12.2@4485,1602
  Bottom Layer w40: S1.3 3382,1038 v1(4398,1038)
P0.0: J1.1 U1.39 | length 502.6
  Top Layer w10: J1.1 1243,1767 1331.89,1678.11 U1.39
P0.1: J1.2 U1.40 | length 457.2
  Top Layer w10: J1.2@1074.57,1658.43 U1.40
P0.2: J1.3 U1.41 | length 542.6
  Top Layer w10: J1.3 1187,1567 1258.43,1638.43 1393,1638.43 ; 1345.74,1638.74 U1.41
P0.3: J1.4 U1.43 | length 519
  Top Layer w10: J1.4@1066,1471 1153,1471 1281.37,1599.37 U1.43
P0.4(T3): R4.2 R9.2 U1.44 | length 2951.7
  Top Layer w10: v1@1381.32,1579.68 U1.44 ; v1(2816,1835) 3309,1835 3412,1938 3412,2082 3460,2130 3573,2130 R9.2
  Top Layer w20: R9.2 R4.2
  Bottom Layer w10: v1(1381,1580) 1315,1646 1315,1763 1388,1836 2815,1836 v1(2816,1835)
P0.5: R5.2 R11.2 U1.45 | length 1490
  Top Layer w10: v1@1310,1560 U1.45 ; v1(1954,2089) R11.2
  Top Layer w20: R5.2@2033,2024 R11.2
  Bottom Layer w10: v1(1302,1568) 1292,1568 1247,1613 1247,1834.72 1325.28,1913 1552.28,1913 1748.28,2109 1934,2109 v1(1954,2089)
P0.6(T4): R3.2 R8.2 U1.46 | length 1574.5
  Top Layer w10: v1@1280,1540.31 U1.46 ; v1(1952,2153) R8.2
  Top Layer w20: R8.2@2034,2154 R3.2
  Bottom Layer w10: v1(1278,1542) 1278,1546 1227,1597 1227,1843 1317,1933 1544,1933 1740,2129 1930,2129 1930,2131 v1(1952,2153)
P0.7: J1.5 U1.47 | length 557.5
  Top Layer w10: J1.5 1146,1367 1299,1520 1494,1520 ; 1465.63,1520.63 U1.47
P1.0（PWM1）: R40.1 U1.48 | length 1304.2
  Top Layer w10: v1(1416,1738) 1416,1858.72 1521,1963.72 1521,2509 1592,2580 R40.1 ; v1@1446.94,1500.94 U1.48
  Bottom Layer w10: v1@1414,1736 1414,1528 v1(1444,1498)
P1.1: J1.6 U1.3 | length 671.7
  Top Layer w10: J1.6 1283,1267 1369,1353 1615,1353 1644,1382 U1.3
P1.2: J1.7 U1.4 | length 750.6
  Top Layer w10: J1.7 1235,1167 1379,1311 1623,1311 1663.68,1351.68 U1.4
P2.2（PWM4）: R47.1 U1.33 | length 2026.7
  Top Layer w10: U1.33 v1(1663.68,1889.68) ; v1(3031,2498) R47.1@3168,2498
  Bottom Layer w10: v1(1663.68,1889.68) 1700,1926 2198.01,1926 2328,2055.99 2328,2348 2478,2498 v1(3031,2498)
P2.4（PWM3）: R48.1 U1.35 | length 2088.7
  Top Layer w10: U1.35 v1(1624.31,1898.31) ; v1(3030,2547) R48.1@3171,2547
  Bottom Layer w10: v1(1624.31,1898.31) 1695,1969 2188,1969 2284,2065 2284,2363 2465,2544 v1@3022,2544
P2.6（PWM2）: R39.1 U1.37 | length 979.7
  Top Layer w10: U1.37 1484.52,1717.48 1441.28,1760.72 1441.28,1855.72 1545,1959.43 1545,2468 1591,2514 R39.1
P2.7: R6.2 R12.2 U1.38 | length 2774.6
  Top Layer w10: v1@1352.2,1697.8 U1.38 ; v1(2816,1802) 3320,1802 3443.11,1925.11 3443.11,2069.11 3484,2110 3570,2110 R12.2
  Top Layer w20: R6.2 R12.2
  Bottom Layer w10: v1@1343,1706 1343,1749 1394,1800 v1@2810,1800
  other v1: 1344,1706
P3.7（INT3）干簧管: J1.8 U1.28 | length 1531.7
  Top Layer w10: v1(1729,1860) 1742.11,1860 1762.11,1840 U1.28
  Bottom Layer w10: J1.8 1222,1067 1352,1197 1352,1570 1285,1637 1285,1802 1343,1860 v1(1729,1860)
POWER-MCU: C3.2 C4.2 C5.2 C31.2 J4.1 J5.1 key1.2 OLED1.2 R1.1 R2.1 R7.1 R10.1 R17.1 R27.1 R33.2 R34.2 U1.15 U5.5 | length 7219
  Top Layer w10: v1(1791,1582) 1791,1567 1817.69,1540.31 U1.15
  Top Layer w20: R17.1@2173,1567 v1(2173,1633) ; R27.1 2535,1146 R33.2 ; v1(2523,1211) 2576,1211 R34.2@2580,1215 ; R33.2@2585,1147 R34.2 ; R10.1 R7.1 ; key1.2 3512,1083 3525,1070 3571,1070 C5.2 3916,1127 3953,1090 4144,1090 4247,1193 R1.1 R2.1 v1(4247,1484) ; C31.2@4776.12,1427.88 U5.5 v1(4850.4,1364.4)
  Bottom Layer w20: 1738,1620 1791,1620 v1(1791,1582) ; 1747,1621 1719,1621 1664,1566 1664,1485 1722,1427 1870,1427 2086,1211 v1(2523,1211) ; v1(2173,1633) 2173,1736.5 ; 3057,1734.5 v1(3057,1885) ; 3314,1736.5 J5.1@3314,2218
  Bottom Layer w40: C3.2@1791.5,1620.94 C4.2 1791.5,1710.5 1817.5,1736.5 2173,1736.5 3057,1734.5 3314,1736.5 3804.5,1736.5 4054,1487 4787,1487 4850.4,1423.6 v1(4850.4,1364.4)
REST: C5.1 key1.1 R16.2 U1.14 | length 1930.3
  Top Layer w10: U1.14 v1@2007,1520.63 ; v1(3434.2,1336.8) key1.1
  Top Layer w20: key1.1 3512,1325 3573,1264 R16.2 C5.1@3631,1184.44
  Bottom Layer w10: v1@2007,1522 2083,1446 3325,1446 v1(3434.2,1336.8)
  other v1: 2008,1523
RXD: R32.2 U1.20 | length 807.2
  Top Layer w10: U1.20 2052.74,1638.74 ; 2053.06,1639.06 2096,1682 2268,1682 2327,1623 2614,1623 R32.2
RXD_1: PPS3.2 R32.1 U6.7 | length 1024.5
  Top Layer w10: R32.1@2717,1653 3074,1653 3144,1583 3379,1583 3398,1602 3398,1626 3383,1641 U6.7
  Top Layer w20: PPS3.2 2670,1460 2717,1507 2717,1644 R32.1
SA0/SD0: J5.5 R10.2 R14.2 U1.22 | length 1997.4
  Top Layer w10: U1.22 1994.11,1678.11 2065,1749 2065,1854 2126,1915 2355,1915 v1(2356,1914) ; J5.5 2963,2164 R10.2@2963,1948 ; R10.2@2952,1947 R10.2 R14.2@3011,1947
  Bottom Layer w10: v1(2356,1914) 2355,1914 2353,1916 2461,2024 2461,2287 2539,2365 2870,2365 2909,2326 J5.5
SCL: OLED1.3 R1.2 U1.8 | length 2988
  Top Layer w10: U1.8 v1@1742.43,1506.43
  Top Layer w20: OLED1.3 4148,1267 R1.2
  Bottom Layer w10: v1(1745,1499) 1906,1499 1960,1553 2507,1553 2567,1493 3810,1493 3920,1383 3920,1164.72 3976.72,1108 4064.28,1108 4101,1144.72 4101,1169 4136,1204 OLED1.3
SCL-1: J5.3 R7.2 R13.2 U1.21 | length 2280.8
  Top Layer w10: U1.21 2019.43,1658.43 2088,1727 2088,1829 2140,1881 v1(2382,1881) ; v1(2858,2325) 3066,2325 3109,2282 J5.3 3161,2166 3161,1947 R7.2 R7.2@3171,1947 ; R13.2@3109,1947 3158,1947 R7.2@3161,1944
  Bottom Layer w10: 2256,1881 v1@2381,1881 ; v1@2377.09,1877.09 v1@2381,1881 ; v1(2382,1881) v1@2381,1881 ; v1@2858,2329 2559,2329 2494,2264 2494,1994 v1@2381,1881
SDA: OLED1.4 R2.2 U1.6 | length 3147.1
  Top Layer w10: U1.6 v1(1703.06,1507)
  Top Layer w20: OLED1.4 4113,1269 4113,1342 4155,1384 R2.2
  Bottom Layer w10: v1(1703.06,1507) 1703.06,1516.06 1723,1536 1769,1536 1786,1519 1897.72,1519 1951.72,1573 2515.28,1573 2575.28,1513 3818.28,1513 3940,1391.28 3940,1173 3985,1128 4056,1128 4081,1153 4081,1171 OLED1.4
SDA/SDI: J5.4 U1.23 | length 1772.9
  Top Layer w10: U1.23 1982.8,1697.8 2045,1760 2045,1868 2121,1944 2122,1943 2123,1944 v1(2337.92,1944)
  Bottom Layer w10: v1(2337.92,1944) 2343,1944 2429,2030 2429,2305.05 2519.95,2396 2950,2396 3009,2337 J5.4
T_VIN: J6.1 J7.2 | length 410
  Top Layer w60: J7.2 4515,3208 4628.5,3094.5 J6.1
TXD: D1.1 U1.19 | length 809.1
  Top Layer w10: U1.19 2067.06,1619.06 2110,1662 2259.72,1662 2318.72,1603 2610,1603 D1.1
TXD_1: D1.2 PPS2.2 U6.6 | length 914.4
  Top Layer w10: D1.2 2852,1633 3065.72,1633 3135.72,1563 3387.28,1563 3419,1594.72 3419,1627 3433,1641 U6.6
  Top Layer w20: PPS2.2 2756,1537 D1.2
"USB D+": R30.2 U6.1 | length 339.2
  Top Layer w10: R30.2 3144,1413 3161,1430 3226,1430 3259,1463 3259,1491 3277,1509 3330,1509 3346,1493 3346,1477 3333,1464 U6.1
"USB D-": R28.2 U6.2 | length 377.5
  Top Layer w10: R28.2 3138,1478 3166,1450 3217.72,1450 3238,1470.28 3238,1498.28 3268.72,1529 3338.28,1529 3367,1500.28 3367,1477 3383,1461 U6.2
V_SNS: C44.1 R43.1 R45.2 U7.7 | length 379.2
  Top Layer w10: U7.7@2255.47,3035.47 U7.7 2288,3057.44 2288,3168 2304,3184 R43.1@2304,3318 ; R43.1 C44.1@2361.44,3320
VCC-CH340: C27.1 C34.2 F1.2 S1.2 U6.5 | length 1134.9
  Top Layer w30: U6.5@3495.41,1652 3601,1652 3685,1568 v1(3685,1439)
  Bottom Layer w30: F1.2 C27.1@3213,1329 ; S1.2 3554,1179 3685,1310 v1(3685,1439)
  Bottom Layer w40: F1.2 3213,1219.47 3300.53,1219.47 S1.2
VREF+: C7.1 R18.2 U1.12 U2.1 U2.2 | length 431.6
  Top Layer w10: U1.12@1825.37,1432 R18.2@2257,1432
XCL: J4.6
XDA: J4.5
XTAL0: C1.1 U1.9 Y1.2 | length 343.1
  Top Layer w10: Y1.2 1759,1198.48 1759,1230 1736,1253 C1.1 1761.5,1294.5 ; 1762.11,1295.11 U1.9
XTAL1: C2.1 U1.10 Y1.1 | length 346.5
  Top Layer w10: 1781.8,1293.8 U1.10 ; 1782.11,1290.89 C2.1 1803,1258 1779,1234 1779,1194 1841,1132 Y1.1
pads on no net: J6.3 P1.0 P1.4 S1.1 U1.1 U1.2 U1.5 U1.7 U1.16 U1.18 U1.25 U1.26 U1.27 U1.29 U1.30 U1.31 U1.32 U1.34 U1.36 U1.42 U4.13 U6.4 U7. U7.0
copper on no net:
  other v1: 4630,1802
  other v2: 2891.55,1149.36 3064.78,1149.36

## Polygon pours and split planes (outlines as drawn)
GND on Top Layer "Top Layer-No Net" (solid, remove dead copper, pour order 0): 742,3621 875,3488 5274,3488
GND on Top Layer "Top Layer-No Net" (solid, remove dead copper, pour order 2): 839,3629 5427,3629 5447,3609 5278,3440 5278,694 552,694 520,726 835,1041 835,3641
GND on Bottom Layer "Top Layer-No Net" (solid, remove dead copper, pour order 4): 746,3665 5342,3665 5443,3564 5455,3552 5455,689 980,689 831,540 758,613 758,3665

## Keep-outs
Keep-Out Layer:
  lines w10: 1003,1965 1003,1003 4919,1003 4919,1964 ; 1003,1967 1496,1967 1496,2425 1006,2425 1003,2428 1003,3513 4919,3513 4919,2424 4435,2424 4435,1966 4917,1966

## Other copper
Top Layer:
  rectangle net NetF1_1: 2846,1310 2924,1383
  rectangle net OUT-5V: 4490,1351 4690,1384
  rectangle net POWER-MCU: 4754,1325 4870,1377
  rectangle net OUT-5V: 4451,1543 4816,1619
  rectangle net NetC6_1: 4115,1792 4234,1821
  rectangle net NetC6_1: 4193,1760 4247,1821
  rectangle net NetC6_1: 4599,1758 4817,1823
  rectangle net EN1: 4117,1842 4523,1946
  rectangle net DRV-6V: 1879,2323 1958,2355
  rectangle net DRV-6V: 1878,2231 1974,2495
  rectangle net DRV-6V: 3404,2203 3487,2465
  rectangle net BOOST_IN: 4199,2889 4313,3371
  rectangle net BOOST_IN: 4208,2889 4510,3067
  rectangle net BOOST_IN: 3620,3283 4219,3312
  rectangle net BOOST_IN: 3683,3307 4254,3373
  rectangle net BOOST_IN: 3674,3307 3683,3328
  rectangle net BOOST_IN: 3664,3307 3674,3320
  rectangle net NetC10_2: 3620,3184 3650,3254
  rectangle net GND: 3483,3281.86 3585,3498
  rectangle net GND: 3558,3438 4823,3499
  rectangle net GND: 2748,3322 2795,3373
  rectangle net GND: 2752,3426 2824,3492
  rectangle net GND: 2211,2809 2242,2918
  rectangle net GND: 2228,2911 2312,2945
  rectangle net GND: 2211,2911 2242,3397
  rectangle net DRV-6V: 1281,2927 1615,3139
  rectangle net GND: 1308,2780 1581,2859
  rectangle net GND: 4566,1201 4738,1326
  rectangle net GND: 4266,1695 4537,1784
  rectangle net GND: 4266,1575 4380,1714
  rectangle net GND: 4189,1575 4266,1658
  rectangle net GND: 3028,1304 3093,1386
  rectangle net GND: 3529,3021 3586,3389
  region net NetC10_2: 3620,3254 3626,3248 3695,3248 3733,3210 3915,3210 3972,3153 3972,2889 3837,2889 3837,3061 3751,3147 3723,3147 3682,3188 3638,3188 3638,3248
  region net 12V-VCC: 3519,3252 3454,3252 3450,3248 3398,3300 2938,3300 2879,3241 2729,3241 2709,3221 2709,3032 2861,3032 2955,3126 2955,3173 2990,3208 3519,3208
  region net GND: 3167,3120 3129,3082 3129,3009 3181,2957 3704,2957 3730,2983 3730,3014 3713,3031 3268,3031 3245,3054 3245,3116 3241,3120
  region net GND: 3502,3288 3476,3288 3393,3371 2844,3371 2792,3319 2792,3360 2747,3405 2787,3445 2787,3493 3485,3493 3502,3476
  region net 12V-VCC: 2293.74,2957 2786,2957 2955,3126 2955,3131 2366,3131 2341,3087 2296,3014
  region net NetC35_1: 2157.91,2957 2087,2957 2022,3022 1957,3022 1953,3018 1953,2905.06 2007.5,2905.06 2039.75,2937.32 2157.91,2937.32
  region net GND: 2298.37,2917.63 2368,2848 2368,2806 2400,2774 2585,2774 2585,2785 2586,2786 2586,2865 2547,2904 2378,2904 2344.68,2937.32 2293.74,2937.32 2293.74,2920.26 2303,2911
Bottom Layer:
  rectangle net NetF1_1: 2845,1309 2924,1384
  rectangle net NetC6_1: 4191,1758 4654,1823
  rectangle net GND: 3029,1305 3156,1386
  rectangle net GND: 4650,3187 4855,3475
